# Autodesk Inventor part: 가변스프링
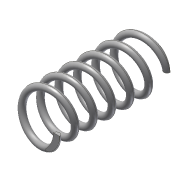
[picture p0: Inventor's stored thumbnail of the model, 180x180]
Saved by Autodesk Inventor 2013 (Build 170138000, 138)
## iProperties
Created: 2020-02
Part Number: 가변스프링
Material: 강철
Document SubType Name: Modeling
Designer: Administrator
Density: 7.85 g/cm^3
Mass: 6.4268 g
Surface Area: 16.6066 cm^2
Volume: 0.818701 cm^3
Author: Administrator
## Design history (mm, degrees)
sketch "스케치1"
  geometry: L1 (0, 0)-(7, 0); L2 (7, 0)-(7, 35.5); L3 (7, 35.5)-(0, 35.5); L4 (0, 35.5)-(0, 0); C1 r 1 at (7, 0)
  constraints: 8 end point, 2 parallel, 1 centre point, 1 coincident, 1 horizontal, 1 perpendicular
  dimensions: "d0" = 14 diameter of L2 L4; "d2" = 35.5 distance of L1.end L2.end (derived); "d3" = 2 diameter of C1
feature "코일1" pitch "d4" = 10; turns "d6" = 6; dims "d5" = 35.5 (= d2), "d7" = 0, angle "d8" = 90 deg, angle "d9" = 90 deg, "d10" = 0, "d11" = 0
sketch "스케치2"
  geometry: L1 (-8, 0)-(-6, 0) reference; 1 further point
  constraints: 1 horizontal alignment
extrude "돌출1" cut sketch "스케치2" stored distance "d12" = 10; taper "d13" = 0 deg
node "작업 평면1"
sketch "스케치3"
  geometry: L1 (1, 0)-(-1, 0) reference; 1 further point
  constraints: 1 horizontal alignment
extrude "돌출2" cut sketch "스케치3" stored distance "d15" = 10; taper "d16" = 0 deg
node "솔리드1"
node "절단 모서리 투영1"
node "절단 모서리 투영2"
other parameters: "d14" = 90 deg
